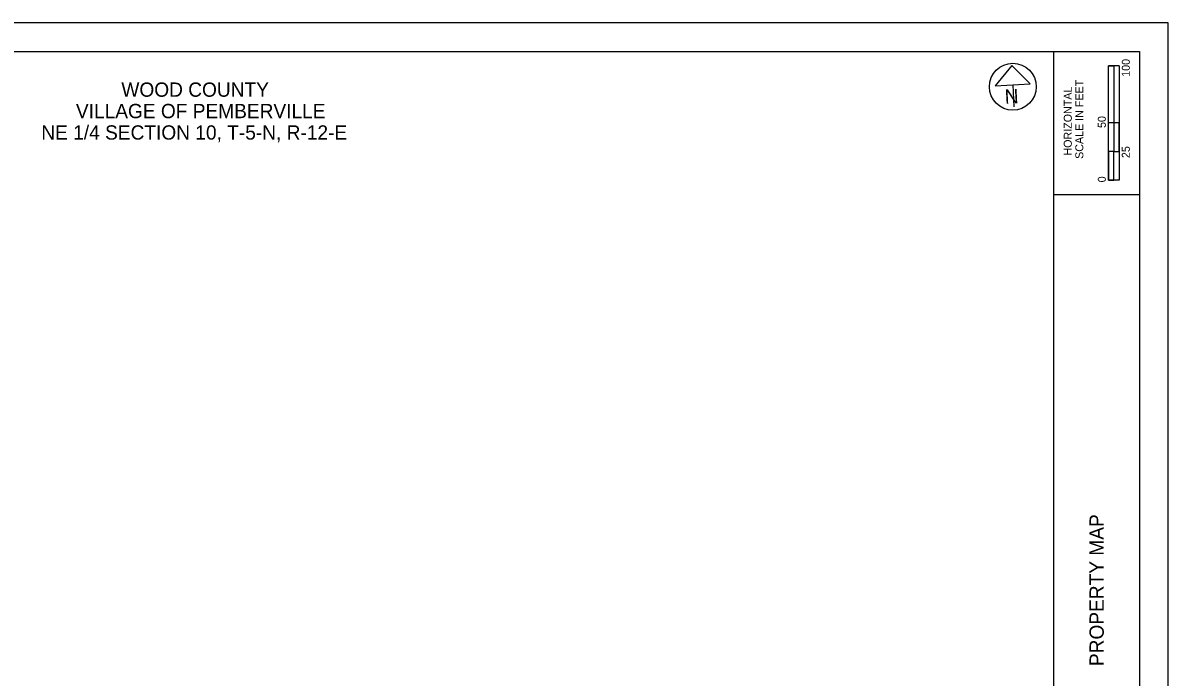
# Model space of a CAD drawing. Extents: x -1 to 34, y 0 to 22.
# Drawn here: x 13.97 to 34, y 10.56 to 22 of the extents above; entities that cross this region are included whole.
import ezdxf

# ---------------------------------------------------------------- set-up
doc = ezdxf.new("R2010")
doc.units = 0
for name, color, linetype in [('CM_Corridor_Final', 7, 'Continuous'), ('CM_Corridor_Range_Final', 7, 'Continuous'), ('MD_P_GRADE_BREAK', 7, 'Continuous'), ('PF_X_Ground_Line', 7, 'Continuous'), ('SC_Scratch5', 7, 'Continuous')]:
    doc.layers.add(name, color=color, linetype=linetype)

msp = doc.modelspace()

# ---------------------------------------------------------------- linework, layer by layer
at = {"layer": 'CM_Corridor_Final'}
for p, q in [((32.957, 19.25), (32.957, 21.25)), ((33.144, 21.25), (32.957, 21.25)), ((32.957, 20.25), (32.957, 21.25)), ((32.957, 21.25), (33.05, 21.25)), ((33.05, 21.25), (33.051, 21.25)), ((33.051, 21.25), (33.051, 20.25)), ((33.144, 21.25), (33.144, 19.25)), ((33.051, 20.25), (32.957, 20.25)), ((33.143, 20.25), (33.05, 20.25)), ((33.05, 20.25), (33.05, 19.75)), ((33.143, 19.75), (33.143, 20.25)), ((33.05, 19.75), (32.957, 19.75)), ((32.957, 19.75), (32.957, 19.25)), ((33.05, 19.75), (33.143, 19.75)), ((33.05, 19.25), (33.05, 19.75)), ((33.144, 19.25), (32.957, 19.25)), ((32.957, 19.25), (33.05, 19.25))]:
    msp.add_line(p, q, dxfattribs=at)
at = {"layer": 'CM_Corridor_Range_Final'}
msp.add_circle((31.284, 20.883), 0.41, dxfattribs=at)
at = {"layer": 'MD_P_GRADE_BREAK'}
for p, q in [((31.264, 21.256), (30.975, 20.899)), ((31.589, 20.932), (31.264, 21.256)), ((30.975, 20.899), (31.589, 20.932)), ((31.282, 20.915), (31.303, 20.529))]:
    msp.add_line(p, q, dxfattribs=at)
msp.add_circle((31.284, 20.883), 0.41, dxfattribs=at)
at = {"layer": 'PF_X_Ground_Line'}
for p, q in [((32, 0.5), (32, 21.5)), ((32, 19), (33.5, 19))]:
    msp.add_line(p, q, dxfattribs=at)
msp.add_lwpolyline([(1.5, 21.5), (33.5, 21.5), (33.5, 0.5), (1.5, 0.5)], close=True, dxfattribs=at)
at = {"layer": 'SC_Scratch5'}
msp.add_lwpolyline([(0, 0), (34, 0), (34, 22), (0, 22)], close=True, dxfattribs=at)

# ---------------------------------------------------------------- texts
at = {"layer": 'CM_Corridor_Final'}
for s, height, p in [('100', 0.14, (33.33, 21.057)), ('HORIZONTAL', 0.14, (32.315, 19.679)), ('SCALE IN FEET', 0.14, (32.517, 19.621)), ('50', 0.14, (32.91, 20.162)), ('25', 0.14, (33.33, 19.635)), ('0', 0.14, (32.91, 19.211)), ('PROPERTY MAP', 0.25, (32.875, 10.748))]:
    msp.add_text(s, height=height, rotation=90, dxfattribs=at).set_placement(p)
at = {"layer": 'MD_P_GRADE_BREAK'}
for s, p in [('WOOD COUNTY', (15.689, 20.708)), ('VILLAGE OF PEMBERVILLE', (14.894, 20.333)), ('NE 1/4 SECTION 10, T-5-N, R-12-E', (14.289, 19.958))]:
    msp.add_text(s, height=0.25, dxfattribs=at).set_placement(p)
msp.add_text('N', height=0.25, rotation=3.059, dxfattribs=at).set_placement((31.148, 20.584))

doc.saveas('drawing.dxf')
